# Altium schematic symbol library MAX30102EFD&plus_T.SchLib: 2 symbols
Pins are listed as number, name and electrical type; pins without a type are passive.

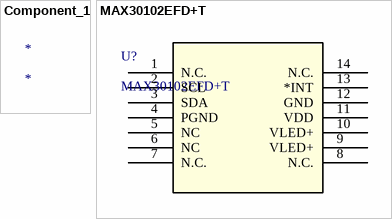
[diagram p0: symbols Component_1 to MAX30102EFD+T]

## Component_1
designator *

## MAX30102EFD+T
designator U?
No Description Available; SourceLibrary: Update_to_database_2021-01-29; Built_By: EMA_UL_Team; Vendor: Maxim Integrated Products
footprint 21-1048_F143A5+1_MXM
pins: 1 N.C., 2 SCL, 3 SDA, 4 PGND, 5 NC, 6 NC, 7 N.C., 8 N.C., 9 VLED+, 10 VLED+, 11 VDD (power), 12 GND, 13 *INT, 14 N.C.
